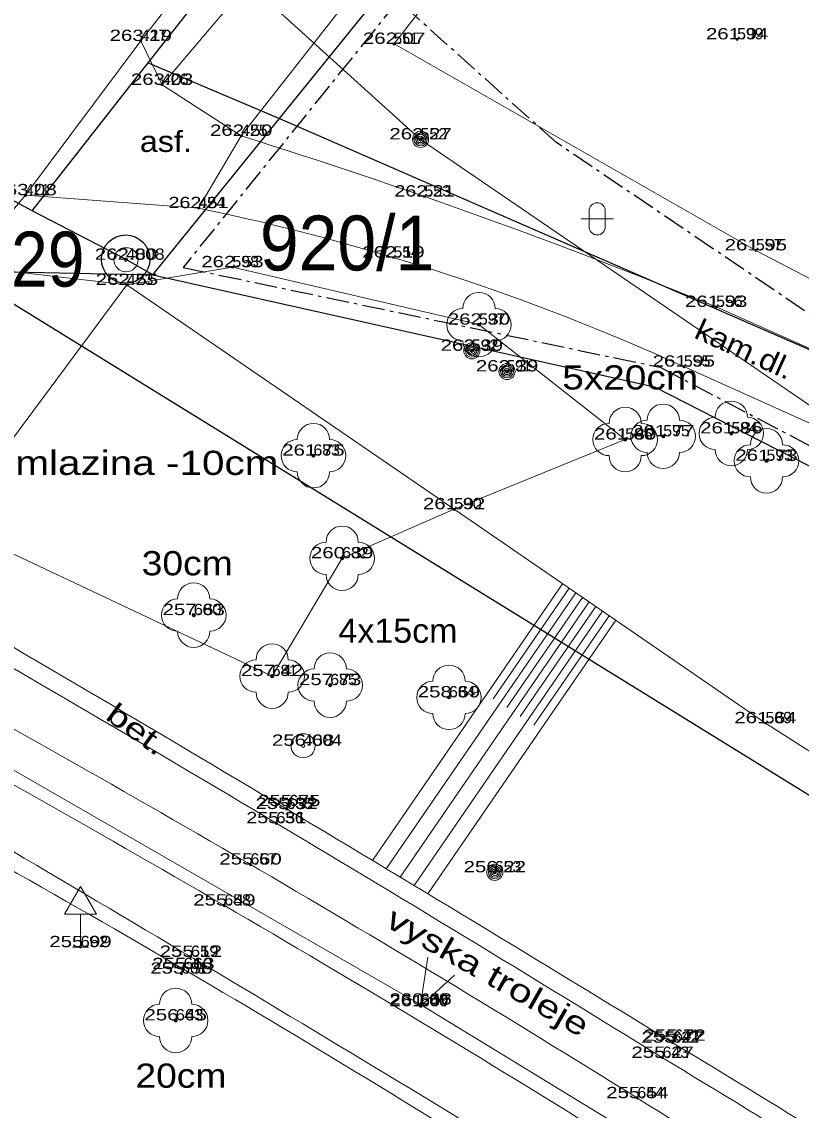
# Model space of a CAD drawing. Extents: x -568530 to -568223, y -1154101 to -1153740.
# Drawn here: x -568401.91 to -568377.75, y -1153942.5 to -1153908.77 of the extents above; entities that cross this region are included whole.
import ezdxf
from ezdxf.enums import TextEntityAlignment as Align

# ---------------------------------------------------------------- set-up
doc = ezdxf.new("R2010")
doc.units = 0
doc.header["$LTSCALE"] = 0.14
doc.header["$PDMODE"] = 32
doc.header["$PDSIZE"] = 0.07
doc.linetypes.add('DOT_DASHED', pattern=[7.7, 5, -1.2, 0.3, -1.2])
for name, color, linetype, lineweight in [('1', 7, 'Continuous', 25), ('10', 7, 'Continuous', 13), ('11', 7, 'Continuous', 13), ('12', 7, 'Continuous', 13), ('14', 7, 'Continuous', 13), ('15', 7, 'Continuous', 13), ('17', 7, 'Continuous', 13), ('21', 7, 'Continuous', 13), ('22', 7, 'Continuous', 13), ('23', 7, 'Continuous', 13), ('25', 7, 'Continuous', 13), ('34', 7, 'Continuous', 13), ('36', 7, 'Continuous', 13), ('4', 7, 'Continuous', 25), ('42', 7, 'Continuous', 13), ('48', 7, 'Continuous', 13), ('51', 7, 'Continuous', 13), ('53', 7, 'Continuous', 13), ('6', 7, 'DOT_DASHED', 25)]:
    doc.layers.add(name, color=color, linetype=linetype, lineweight=lineweight)
for name, color, linetype in [('13', 7, 'Continuous'), ('20', 7, 'Continuous'), ('40', 7, 'Continuous')]:
    doc.layers.add(name, color=color, linetype=linetype)

msp = doc.modelspace()

# ---------------------------------------------------------------- linework, layer by layer
at = {"layer": '1'}
for points in [[(-568397.85, -1153916.62), (-568348.36, -1153855.52), (-568306.73, -1153803.52), (-568266.23, -1153754.08)], [(-568397.85, -1153916.62), (-568398.69, -1153916.13), (-568401.59, -1153914.63), (-568407.5, -1153911.44), (-568412.5, -1153908.68)], [(-568393.92, -1153911.77), (-568368.85, -1153922.7), (-568351.96, -1153932.04), (-568287.81, -1153983.13)], [(-568397.85, -1153916.62), (-568382.3, -1153920.09), (-568354.17, -1153934.45), (-568269.88, -1154000.68)]]:
    msp.add_lwpolyline(points, dxfattribs=at)
at = {"layer": '10'}
msp.add_lwpolyline([(-568341.41, -1153838.94), (-568349.83, -1153849.41), (-568360.25, -1153862.43), (-568369.78, -1153874.42), (-568378.19, -1153884.73), (-568386.01, -1153894.27), (-568392.67, -1153902.27), (-568398.22, -1153909.37), (-568401.79, -1153914.15), (-568403.6, -1153916.28)], dxfattribs=at)
at = {"layer": '11'}
msp.add_line((-568381.39, -1153919.46), (-568366.54, -1153926.14), dxfattribs=at)
for points in [[(-568377.44, -1153885.3), (-568384.74, -1153895.11), (-568391.27, -1153903.31), (-568397.56, -1153910.73)], [(-568398.22, -1153909.37), (-568397.56, -1153910.73), (-568395.11, -1153912.31)], [(-568401.79, -1153914.15), (-568396.43, -1153914.55), (-568395.11, -1153912.31)], [(-568346.35, -1153936.33), (-568354.63, -1153930.38), (-568365.47, -1153924.26), (-568380.39, -1153917.61)]]:
    msp.add_lwpolyline(points, dxfattribs=at)
for centre, radius, start, end in [((-568450.7473, -1154089.926), 186.1261, 67.78962, 72.60711), ((-568410.9033, -1153984.3733), 71.3076, 65.55079, 78.28935), ((-569009.5906, -1154964.079), 1200.8724, 58.47781, 59.85365), ((-568847.5367, -1154693.8111), 885.2023, 58.27428, 60.13925), ((-568987.7107, -1154929.3603), 1154.3916, 58.50566, 59.89077), ((-568598.8116, -1154282.7187), 399.3866, 57.62556, 61.60266), ((-568603.2448, -1154307.4258), 428.6782, 55.61365, 58.88779), ((-568594.3404, -1154293.2988), 411.4198, 55.52877, 58.93604)]:
    msp.add_arc(centre, radius, start, end, dxfattribs=at)
for p in [(-568398.22, -1153909.37), (-568390.37, -1153909.46), (-568379.74, -1153909.32), (-568397.56, -1153910.73), (-568395.11, -1153912.31), (-568389.55, -1153912.42), (-568401.79, -1153914.15), (-568389.43, -1153914.19), (-568396.43, -1153914.55), (-568379.16, -1153915.86), (-568390.39, -1153916.08), (-568395.38, -1153916.38), (-568398.65, -1153916.93), (-568380.39, -1153917.61), (-568387.74, -1153918.16), (-568387.96, -1153918.97), (-568381.39, -1153919.46), (-568386.87, -1153919.61), (-568379.92, -1153921.53), (-568383.21, -1153921.72), (-568382.03, -1153921.62), (-568392.87, -1153922.22), (-568378.83, -1153922.38), (-568388.51, -1153923.88), (-568391.98, -1153925.4), (-568396.58, -1153927.16), (-568394.15, -1153929.05), (-568392.35, -1153929.33), (-568388.67, -1153929.71), (-568378.86, -1153930.51), (-568393.7, -1153933.17), (-568393.62, -1153933.08), (-568394.02, -1153933.61), (-568394.82, -1153934.89), (-568387.25, -1153935.13), (-568395.63, -1153936.16), (-568400.09, -1153937.45), (-568396.67, -1153937.75), (-568396.9, -1153938.13), (-568396.96, -1153938.27), (-568389.55, -1153939.23), (-568389.55, -1153939.28), (-568397.14, -1153939.72), (-568381.74, -1153940.41), (-568381.68, -1153940.35), (-568382.05, -1153940.88), (-568382.83, -1153942.13)]:
    msp.add_point(p, dxfattribs=at)
at = {"layer": '12'}
for centre, radius, start, end in [((-568635.0051, -1154346.2032), 476.306, 58.03243, 61.43134), ((-568645.0661, -1154364.1594), 495.3805, 58.1384, 61.39848), ((-568708.2241, -1154467.802), 618.2333, 55.97737, 58.24225)]:
    msp.add_arc(centre, radius, start, end, dxfattribs=at)
at = {"layer": '14'}
msp.add_line((-568398.65, -1153916.93), (-568403.47, -1153916.36), dxfattribs=at)
for points in [[(-568395.11, -1153912.31), (-568389.39, -1153905.01), (-568382.04, -1153896.57), (-568374.93, -1153888.14), (-568366.7, -1153877.32), (-568357.21, -1153865.06), (-568347.39, -1153851.22), (-568338.19, -1153841.21)], [(-568354.85, -1153943.42), (-568357.37, -1153943.81), (-568368.01, -1153937.43), (-568378.86, -1153930.51), (-568388.51, -1153923.88), (-568398.65, -1153916.93)]]:
    msp.add_lwpolyline(points, dxfattribs=at)
at = {"layer": '15'}
for p, q in [((-568385.15, -1153926.188), (-568391.042, -1153934.763)), ((-568384.738, -1153926.471), (-568390.612, -1153935.021)), ((-568384.944, -1153926.33), (-568387.297, -1153929.755)), ((-568384.532, -1153926.613), (-568386.878, -1153930.028)), ((-568384.326, -1153926.754), (-568390.183, -1153935.279)), ((-568384.12, -1153926.896), (-568386.46, -1153930.301)), ((-568383.914, -1153927.038), (-568389.754, -1153935.538)), ((-568383.708, -1153927.179), (-568386.041, -1153930.574)), ((-568383.502, -1153927.321), (-568389.325, -1153935.796))]:
    msp.add_line(p, q, dxfattribs=at)
at = {"layer": '21'}
for centre, radius in [((-568398.68, -1153916.15), 0.375), ((-568398.68, -1153916.15), 0.05), ((-568393.19, -1153931.21), 0.375), ((-568393.19, -1153931.21), 0.05)]:
    msp.add_circle(centre, radius, dxfattribs=at)
at = {"layer": '22'}
for centre in [(-568387.74, -1153918.16), (-568382.03, -1153921.62), (-568379.92, -1153921.53), (-568383.21, -1153921.72), (-568392.87, -1153922.22), (-568378.83, -1153922.38), (-568391.98, -1153925.4), (-568396.58, -1153927.16), (-568394.15, -1153929.05), (-568392.35, -1153929.33), (-568388.67, -1153929.71), (-568397.14, -1153939.72)]:
    msp.add_circle(centre, 0.05, dxfattribs=at)
for centre, start, end in [((-568387.74, -1153917.66), 0, 180), ((-568388.24, -1153918.16), 90, 270), ((-568387.24, -1153918.16), 270, 90), ((-568387.74, -1153918.66), 180, 0), ((-568379.92, -1153921.03), 0, 180), ((-568383.21, -1153921.22), 0, 180), ((-568382.03, -1153921.12), 0, 180), ((-568392.87, -1153921.72), 0, 180), ((-568383.71, -1153921.72), 90, 270), ((-568382.53, -1153921.62), 90, 270), ((-568382.71, -1153921.72), 270, 90), ((-568381.53, -1153921.62), 270, 90), ((-568380.42, -1153921.53), 90, 270), ((-568379.42, -1153921.53), 270, 90), ((-568378.83, -1153921.88), 0, 180), ((-568393.37, -1153922.22), 90, 270), ((-568392.37, -1153922.22), 270, 90), ((-568379.33, -1153922.38), 90, 270), ((-568378.33, -1153922.38), 270, 90), ((-568383.21, -1153922.22), 180, 0), ((-568382.03, -1153922.12), 180, 0), ((-568379.92, -1153922.03), 180, 0), ((-568392.87, -1153922.72), 180, 0), ((-568378.83, -1153922.88), 180, 0), ((-568391.98, -1153924.9), 0, 180), ((-568392.48, -1153925.4), 90, 270), ((-568391.48, -1153925.4), 270, 90), ((-568391.98, -1153925.9), 180, 0), ((-568396.58, -1153926.66), 0, 180), ((-568397.08, -1153927.16), 90, 270), ((-568396.08, -1153927.16), 270, 90), ((-568396.58, -1153927.66), 180, 0), ((-568394.15, -1153928.55), 0, 180), ((-568394.65, -1153929.05), 90, 270), ((-568393.65, -1153929.05), 270, 90), ((-568392.35, -1153928.83), 0, 180), ((-568392.85, -1153929.33), 90, 270), ((-568391.85, -1153929.33), 270, 90), ((-568388.67, -1153929.21), 0, 180), ((-568389.17, -1153929.71), 90, 270), ((-568388.17, -1153929.71), 270, 90), ((-568394.15, -1153929.55), 180, 0), ((-568392.35, -1153929.83), 180, 0), ((-568388.67, -1153930.21), 180, 0), ((-568397.14, -1153939.22), 0, 180), ((-568397.64, -1153939.72), 90, 270), ((-568396.64, -1153939.72), 270, 90), ((-568397.14, -1153940.22), 180, 0)]:
    msp.add_arc(centre, 0.5, start, end, dxfattribs=at)
at = {"layer": '23'}
for points in [[(-568354.04, -1153929.41), (-568364.61, -1153923.44), (-568379.16, -1153915.86), (-568390.37, -1153909.46), (-568387.81, -1153906.15), (-568381.36, -1153897.16), (-568374.28, -1153888.42), (-568365.82, -1153877.84), (-568356.68, -1153865.62), (-568346.38, -1153852.31), (-568338.19, -1153841.21)], [(-568398.65, -1153916.93), (-568395.38, -1153916.38), (-568387.74, -1153918.16), (-568383.21, -1153921.72), (-568388.51, -1153923.88)], [(-568398.65, -1153916.93), (-568404.16, -1153924.33), (-568394.15, -1153929.05)], [(-568394.15, -1153929.05), (-568391.98, -1153925.4), (-568388.51, -1153923.88)]]:
    msp.add_lwpolyline(points, dxfattribs=at)
at = {"layer": '25'}
for centre, radius in [((-568389.55, -1153912.42), 0.25), ((-568389.55, -1153912.42), 0.2), ((-568389.55, -1153912.42), 0.15), ((-568389.55, -1153912.42), 0.1), ((-568389.55, -1153912.42), 0.05), ((-568387.96, -1153918.97), 0.25), ((-568387.96, -1153918.97), 0.2), ((-568387.96, -1153918.97), 0.15), ((-568387.96, -1153918.97), 0.1), ((-568387.96, -1153918.97), 0.05), ((-568386.87, -1153919.61), 0.25), ((-568386.87, -1153919.61), 0.2), ((-568386.87, -1153919.61), 0.15), ((-568386.87, -1153919.61), 0.1), ((-568386.87, -1153919.61), 0.05), ((-568387.25, -1153935.13), 0.25), ((-568387.25, -1153935.13), 0.2), ((-568387.25, -1153935.13), 0.15), ((-568387.25, -1153935.13), 0.1), ((-568387.25, -1153935.13), 0.05)]:
    msp.add_circle(centre, radius, dxfattribs=at)
at = {"layer": '25', "lineweight": 25}
for radius in [0.75, 0.032]:
    msp.add_circle((-568398.69, -1153916.13), radius, dxfattribs=at)
at = {"layer": '34'}
for p, q in [((-568400.09, -1153936.432), (-568400.09, -1153937.45)), ((-568400.34, -1153937.45), (-568399.84, -1153937.45))]:
    msp.add_line(p, q, dxfattribs=at)
msp.add_lwpolyline([(-568400.59, -1153936.432), (-568399.59, -1153936.432), (-568400.09, -1153935.566)], close=True, dxfattribs=at)
at = {"layer": '36'}
for p, q in [((-568384.326, -1153914.63), (-568384.326, -1153915.13)), ((-568383.826, -1153914.63), (-568383.826, -1153915.13)), ((-568384.576, -1153914.88), (-568383.576, -1153914.88))]:
    msp.add_line(p, q, dxfattribs=at)
for centre, start, end in [((-568384.0761, -1153914.6315), 0, 180), ((-568384.0761, -1153915.1315), 180, 0)]:
    msp.add_arc(centre, 0.25, start, end, dxfattribs=at)
at = {"layer": '4'}
for p, q in [((-568397.99, -1153910.05), (-568393.92, -1153911.77)), ((-568403.83, -1153916.49), (-568397.85, -1153916.62))]:
    msp.add_line(p, q, dxfattribs=at)
for points in [[(-568401.59, -1153914.63), (-568397.99, -1153910.05), (-568332.4, -1153826.72), (-568306.48, -1153794.28), (-568270.78, -1153751.53)], [(-568416.66, -1153938.36), (-568411.09, -1153926.18), (-568408.89, -1153922.6), (-568403.83, -1153916.49), (-568364.99, -1153940.47), (-568354.7, -1153940.43), (-568327.96, -1153959.28), (-568308.58, -1153974.27), (-568269.22, -1154006.01)]]:
    msp.add_lwpolyline(points, dxfattribs=at)
at = {"layer": '48'}
for p, q in [((-568389.55, -1153939.23), (-568389.324, -1153937.764)), ((-568389.55, -1153939.28), (-568388.497, -1153938.314))]:
    msp.add_line(p, q, dxfattribs=at)
at = {"layer": '51'}
msp.add_lwpolyline([(-568419.22, -1153887.66), (-568408.38, -1153895.39), (-568389.55, -1153912.42), (-568363.64, -1153930.12), (-568330.76, -1153952.92)], dxfattribs=at)
at = {"layer": '53'}
msp.add_lwpolyline([(-568433.578, -1153915.068), (-568419.78, -1153922.17), (-568410.54, -1153927.14), (-568389.55, -1153939.23), (-568371.805, -1153950.061), (-568349.435, -1153965.343)], dxfattribs=at)
at = {"layer": '6'}
for p, q in [((-568390.25, -1153908.12), (-568396.91, -1153916.39)), ((-568396.91, -1153916.39), (-568382.13, -1153919.48)), ((-568382.13, -1153919.48), (-568353.63, -1153934.41))]:
    msp.add_line(p, q, dxfattribs=at)
msp.add_lwpolyline([(-568292.75, -1153788.12), (-568342.85, -1153941.3), (-568385.34, -1153912.52), (-568390.25, -1153908.12)], dxfattribs=at)

# ---------------------------------------------------------------- texts
at = {"layer": '12'}
for s, width, p in [('263.19', 1.35, (-568398.22, -1153909.37)), ('261.94', 1.35, (-568379.74, -1153909.32)), ('262.07', 1.35, (-568390.37, -1153909.46)), ('263.03', 1.35, (-568397.56, -1153910.73)), ('262.50', 1.35, (-568395.1095, -1153912.31)), ('262.27', 1.35, (-568389.55, -1153912.42)), ('263.08', 1.35, (-568401.79, -1153914.15)), ('262.21', 1.3, (-568389.43, -1153914.19)), ('262.51', 1.3, (-568396.43, -1153914.55)), ('262.19', 1.35, (-568390.39, -1153916.08)), ('261.95', 1.35, (-568379.1605, -1153915.86)), ('262.53', 1.35, (-568395.38, -1153916.38)), ('262.55', 1.35, (-568398.6505, -1153916.93)), ('261.93', 1.35, (-568380.39, -1153917.61)), ('262.30', 1.35, (-568387.7395, -1153918.16)), ('262.39', 1.35, (-568387.96, -1153918.97)), ('261.95', 1.35, (-568381.3905, -1153919.46)), ('262.39', 1.35, (-568386.87, -1153919.61)), ('261.86', 1.35, (-568379.92, -1153921.53)), ('261.80', 1.35, (-568383.2095, -1153921.72)), ('261.77', 1.35, (-568382.03, -1153921.62)), ('261.75', 1.35, (-568392.8705, -1153922.22)), ('261.73', 1.35, (-568378.83, -1153922.38)), ('261.92', 1.35, (-568388.51, -1153923.88)), ('260.39', 1.35, (-568391.98, -1153925.4)), ('257.63', 1.35, (-568396.58, -1153927.16)), ('257.42', 1.35, (-568394.15, -1153929.05)), ('257.73', 1.35, (-568392.35, -1153929.33)), ('258.69', 1.35, (-568388.67, -1153929.71)), ('261.64', 1.35, (-568378.86, -1153930.51)), ('255.32', 1.35, (-568393.7, -1153933.17)), ('255.75', 1.35, (-568393.6205, -1153933.08)), ('255.31', 1.3, (-568394.02, -1153933.61)), ('255.60', 1.35, (-568394.8195, -1153934.89)), ('256.22', 1.35, (-568387.25, -1153935.13)), ('255.49', 1.35, (-568395.63, -1153936.16)), ('255.99', 1.35, (-568400.09, -1153937.45)), ('255.12', 1.35, (-568396.67, -1153937.75)), ('255.56', 1.35, (-568396.96, -1153938.27)), ('255.13', 1.35, (-568396.9, -1153938.13)), ('260.66', 1.35, (-568389.55, -1153939.23)), ('261.07', 1.35, (-568389.55, -1153939.28)), ('256.45', 1.35, (-568397.1405, -1153939.72)), ('255.27', 1.35, (-568381.74, -1153940.41)), ('255.72', 1.35, (-568381.68, -1153940.35)), ('255.27', 1.35, (-568382.05, -1153940.88)), ('255.54', 1.35, (-568382.83, -1153942.13))]:
    msp.add_text(s, height=0.35, dxfattribs=dict(at, width=width)).set_placement(p, align=Align.CENTER)
at = {"layer": '13'}
for s, width, p in [('427', 1.05, (-568398.22, -1153909.37)), ('599', 1.05, (-568379.74, -1153909.32)), ('551', 0.95, (-568390.37, -1153909.46)), ('426', 1.05, (-568397.56, -1153910.73)), ('425', 1.05, (-568395.11, -1153912.31)), ('552', 1.05, (-568389.55, -1153912.42)), ('421', 0.95, (-568401.79, -1153914.15)), ('553', 1.05, (-568389.43, -1153914.19)), ('424', 1.05, (-568396.43, -1153914.55)), ('554', 1.05, (-568390.39, -1153916.08)), ('557', 1.05, (-568379.16, -1153915.86)), ('598', 1.05, (-568395.38, -1153916.38)), ('423', 1.05, (-568398.65, -1153916.93)), ('556', 1.05, (-568380.39, -1153917.61)), ('597', 1.05, (-568387.74, -1153918.16)), ('592', 1.05, (-568387.96, -1153918.97)), ('555', 1.05, (-568381.39, -1153919.46)), ('591', 0.95, (-568386.87, -1153919.61)), ('594', 1.05, (-568379.92, -1153921.53)), ('596', 1.1, (-568383.21, -1153921.72)), ('595', 1.05, (-568382.03, -1153921.62)), ('683', 1.05, (-568392.87, -1153922.22)), ('593', 1.05, (-568378.83, -1153922.38)), ('590', 1.1, (-568388.51, -1153923.88)), ('682', 1.05, (-568391.98, -1153925.4)), ('680', 1.1, (-568396.58, -1153927.16)), ('685', 1.05, (-568392.35, -1153929.33)), ('684', 1.05, (-568388.67, -1153929.71)), ('589', 1.05, (-568378.86, -1153930.51)), ('655', 1.05, (-568393.7, -1153933.17)), ('654', 1.05, (-568393.62, -1153933.08)), ('656', 1.1, (-568394.02, -1153933.61)), ('657', 1.05, (-568394.82, -1153934.89)), ('653', 1.05, (-568387.25, -1153935.13)), ('658', 1.05, (-568395.63, -1153936.16)), ('662', 1.1, (-568400.09, -1153937.45)), ('659', 1.1, (-568396.67, -1153937.75)), ('660', 1.15, (-568396.9, -1153938.13)), ('639', 1.1, (-568389.55, -1153939.23)), ('640', 1.1, (-568389.55, -1153939.28)), ('663', 1.1, (-568397.14, -1153939.72)), ('642', 1.05, (-568381.74, -1153940.41)), ('643', 1.05, (-568382.05, -1153940.88)), ('644', 1.05, (-568382.83, -1153942.13))]:
    msp.add_text(s, height=0.35, dxfattribs=dict(at, width=width)).set_placement(p)
for s, p in [('681', (-568394.15, -1153929.05)), ('661', (-568396.96, -1153938.27)), ('641', (-568381.68, -1153940.35))]:
    msp.add_text(s, height=0.35, dxfattribs=at).set_placement(p)
at = {"layer": '17', "width": 0.9}
msp.add_text('229', height=1.7, dxfattribs=at).set_placement((-568399.965, -1153916.98), align=Align.RIGHT)
at = {"layer": '20', "width": 0.95}
msp.add_text('920/1', height=1.7, dxfattribs=at).set_placement((-568394.53, -1153916.48))
at = {"layer": '22', "width": 1.35}
for s, p in [('262.80', (-568398.6795, -1153916.15)), ('256.68', (-568393.19, -1153931.21))]:
    msp.add_text(s, height=0.35, dxfattribs=at).set_placement(p, align=Align.CENTER)
at = {"layer": '23', "width": 1.15}
for s, p in [('4008', (-568398.68, -1153916.15)), ('4004', (-568393.19, -1153931.21))]:
    msp.add_text(s, height=0.35, dxfattribs=at).set_placement(p)
at = {"layer": '40', "width": 1.15}
msp.add_text('asf.', height=0.65, dxfattribs=at).set_placement((-568398.249, -1153912.808))
at = {"layer": '40'}
for s, rotation, width, p in [('kam.dl.', 335.605, 1.15, (-568381.11, -1153918.552)), ('bet.', 323.922, 1.4, (-568399.356, -1153930.362))]:
    msp.add_text(s, height=0.65, rotation=rotation, dxfattribs=dict(at, width=width)).set_placement(p)
at = {"layer": '42'}
for s, width, p in [('5x20cm', 1.2, (-568383.055, -1153920.17)), ('mlazina -10cm', 1.25, (-568398.032, -1153922.818)), ('30cm', 1.15, (-568396.783, -1153925.928)), ('4x15cm', 1.05, (-568390.251, -1153928.019)), ('20cm', 1.15, (-568396.978, -1153941.807))]:
    msp.add_text(s, height=0.75, dxfattribs=dict(at, width=width)).set_placement(p, align=Align.CENTER)
at = {"layer": '48', "width": 1.35}
msp.add_text('vyska troleje', height=0.7, rotation=330.341, dxfattribs=at).set_placement((-568387.6342, -1153938.5185), align=Align.CENTER)

doc.saveas('drawing.dxf')
